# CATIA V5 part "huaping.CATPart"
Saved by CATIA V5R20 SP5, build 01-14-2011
Part number: 花瓶
Material "Sunset"
Material "Water": density 1000 kg/m3
Bounding box of the stored display mesh (mm): x -80 to 80, y -80 to 79.919, z 0 to 211.914
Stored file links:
  E:\姜浩然03.08\huaping.CATPart
  C:\Program Files\Dassault Systemes\B20\intel_a\startup\materials\Catalog.CATMaterial
  C:\Program Files\Dassault Systemes\B20\intel_a\startup\materials\sunset.jpg
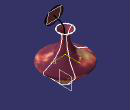
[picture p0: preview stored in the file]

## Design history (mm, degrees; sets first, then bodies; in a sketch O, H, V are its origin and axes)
Body1 (main body), material "Sunset"
  Plane1: type Offset, RefPlane xy-plane, Offset 20
  Set1
    Plane2: type Offset, RefPlane xy-plane, Offset 40 {= Plane1.Offset+`Plane2.相对Offset`}
    Plane3: type Offset, RefPlane xy-plane, Offset 60 {= Plane2.Offset+`Plane3.相对Offset`}
    Plane4: type Offset, RefPlane xy-plane, Offset 80 {= Plane3.Offset+`Plane4.相对Offset`}
    Plane5: type Offset, RefPlane xy-plane, Offset 100 {= Plane4.Offset+`Plane5.相对Offset`}
    Plane6: type Offset, RefPlane xy-plane, Offset 120 {= Plane5.Offset+`Plane6.相对Offset`}
    Plane7: type Offset, RefPlane xy-plane, Offset 140 {= Plane6.Offset+`Plane7.相对Offset`}
    Plane8: type Offset, RefPlane xy-plane, Offset 160 {= Plane7.Offset+`Plane8.相对Offset`}
  Sketch1 on Plane4, origin (0, 0, 80), H (1, 0, 0), V (0, 1, 0)
  Sketch2 on Plane4, origin (0, 0, 80), H (1, 0, 0), V (0, 1, 0)
  Sketch3 on Plane8, origin (0, 0, 160), H (1, 0, 0), V (0, 1, 0)
    circle A1 centre (0, 0) radius 25
  Sketch4 on Plane7, origin (0, 0, 140), H (1, 0, 0), V (0, 1, 0)
    circle A1 centre (0, 0) radius 12
  Sketch5 on Plane6, origin (0, 0, 120), H (1, 0, 0), V (0, 1, 0)
    circle A1 centre (0, 0) radius 15
  Sketch6 on Plane5, origin (0, 0, 100), H (1, 0, 0), V (0, 1, 0)
    circle A1 centre (0, 0) radius 25
  Sketch7 on Plane4, origin (0, 0, 80), H (1, 0, 0), V (0, 1, 0)
    circle A1 centre (0, 0) radius 45
  Sketch8 on Plane3, origin (0, 0, 60), H (1, 0, 0), V (0, 1, 0)
    circle A1 centre (0, 0) radius 80
  Sketch9 on Plane2, origin (0, 0, 40), H (1, 0, 0), V (0, 1, 0)
    circle A1 centre (0, 0) radius 60
  Sketch10 on Plane1, origin (0, 0, 20), H (1, 0, 0), V (0, 1, 0)
    circle A1 centre (0, 0) radius 40
  Sketch11 on xy-plane, origin (0, 0, 0), H (1, 0, 0), V (0, 1, 0)
    circle A1 centre (0, 0) radius 20
    point P1 (20, 0)
    coincidence: A1 P1, P1 H
  Loft1: solid, Sections (Sketch3; Sketch4; Sketch5; Sketch6; Sketch7; Sketch8; Sketch9; Sketch10; Sketch11)
  Shell1: ExtOffset 0, Face face of Loft1, IntOffset 1
Body2, material "Water"
  Sketch12 on yz-plane, origin (0, 0, 0), H (0, 1, 0), V (0, 0, 1)
    axis line L1 (0, 0) -> (0, 191.7666)
    point P2 (0, 66.3799)
    line L2 (0, 66.3799) -> (60.8957, 66.3799)
    line L3 (60.8957, 66.3799) -> (70.5438, 60.5399)
    line L4 (70.5438, 60.5399) -> (20.2357, 5.5759)
    line L5 (20.2357, 5.5759) -> (0, 5.5759)
    point P6 (0, 5.5759)
    vertical: L1 V
    coincidence: P2 L1, P6 L1
    horizontal: L2 H, L5 H
  Shaft1: profile Sketch12, axis Sketch12.L1, angle 360
Body3
  Sketch13 on yz-plane, origin (0, 0, 0), H (0, 1, 0), V (0, 0, 1)
    spline S1 through (-41.4652, 181.9162) (-5.7615, 163.6464) (-26.299, 72.612) (-11.1329, 20.3224) (28.3623, 24.4174)
  Plane9: type Normal, Curve Sketch13, RefPoint vertex of Sketch13
  Sketch14 on Plane9, origin (0, -76.3855, 16.0851), H (-1, 0, 0), V (0, 0.2061, 0.9785)
    circle A1 centre (0, 169.4999) radius 1
    point P1 (0, 169.4999)
    coincidence: P1 V
  Rib1: profile Sketch14, centre curve Sketch13
  Sketch15 on Plane9, origin (0, -76.3855, 16.0851), H (-1, 0, 0), V (0, 0.2061, 0.9785)
    circle A1 centre (0, 168.9164) radius 31.2071
    point P1 (0, 168.9164)
    coincidence: P1 V
  Pad1: profile Sketch15, direction (0, 0.9785, -0.2061), length 1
